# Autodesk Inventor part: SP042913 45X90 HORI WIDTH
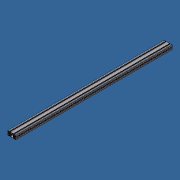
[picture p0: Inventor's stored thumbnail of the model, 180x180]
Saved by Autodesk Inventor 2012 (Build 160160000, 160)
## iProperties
Created: 2013-04
Part Number: SP042913 45X90 HORI WIDTH
Material: Aluminum-6061
Description: PROFILE 45X90 F
Document SubType Name: Modeling
Designer: Admin
Stock Number: 20.1032 PROFILE 45X90 F
Density: 2.71 g/cm^3
FINISH: CLEAR ANODIZED
Author: Admin
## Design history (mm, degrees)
sketch "Sketch1"
  geometry: L1 (43, -8.8)-(43, -15.5) reference; L2 (38, -20.5)-(31.3, -20.5) reference; L3 (31.3, -20.5)-(31.3, -13.8) reference; L4 (36.3, -8.8)-(43, -8.8) reference; L5 (-43, 8.8)-(-43, 15.5) reference; L6 (-38, 20.5)-(-31.3, 20.5) reference; L7 (-31.3, 20.5)-(-31.3, 13.8) reference; L8 (-36.3, 8.8)-(-43, 8.8) reference; L9 (43, 15.5)-(43, 8.8) reference; L10 (43, 8.8)-(36.3, 8.8) reference; L11 (31.3, 13.8)-(31.3, 20.5) reference; L12 (31.3, 20.5)-(38, 20.5) reference; L13 (-43, -15.5)-(-43, -8.8) reference; L14 (-43, -8.8)-(-36.3, -8.8) reference; L15 (-31.3, -13.8)-(-31.3, -20.5) reference; L16 (-31.3, -20.5)-(-38, -20.5) reference; L17 (-25.682, -4.596)-(-27.096, -3.182) reference; L18 (-27.096, -3.182)-(-25.763, -1.849) reference; L19 (-25.763, 1.849)-(-27.096, 3.182) reference; L20 (-27.096, 3.182)-(-25.682, 4.596) reference; L21 (-25.682, 4.596)-(-24.349, 3.263) reference; L22 (-20.651, 3.263)-(-19.318, 4.596) reference; L23 (-19.318, 4.596)-(-17.904, 3.182) reference; L24 (-17.904, 3.182)-(-19.237, 1.849) reference; L25 (-19.237, -1.849)-(-17.904, -3.182) reference; L26 (-17.904, -3.182)-(-19.318, -4.596) reference; L27 (-19.318, -4.596)-(-20.651, -3.263) reference; L28 (-24.349, -3.263)-(-25.682, -4.596) reference; L29 (19.318, -4.596)-(17.904, -3.182) reference; L30 (17.904, -3.182)-(19.237, -1.849) reference; L31 (19.237, 1.849)-(17.904, 3.182) reference; L32 (17.904, 3.182)-(19.318, 4.596) reference; L33 (19.318, 4.596)-(20.651, 3.263) reference; L34 (24.349, 3.263)-(25.682, 4.596) reference; L35 (25.682, 4.596)-(27.096, 3.182) reference; L36 (27.096, 3.182)-(25.763, 1.849) reference; L37 (25.763, -1.849)-(27.096, -3.182) reference; L38 (27.096, -3.182)-(25.682, -4.596) reference; L39 (25.682, -4.596)-(24.349, -3.263) reference; L40 (20.651, -3.263)-(19.318, -4.596) reference; L41 (-14.286, -7.786)-(-14.914, -7.157) reference; L42 (-15.5, -5.743)-(-15.5, 5.743) reference; L43 (-14.914, 7.157)-(-14.286, 7.786) reference; L44 (-13.7, 9.2)-(-13.7, 20.5) reference; L45 (-13.7, 20.5)-(13.7, 20.5) reference; L46 (13.7, 20.5)-(13.7, 9.2) reference; L47 (14.286, 7.786)-(14.914, 7.157) reference; L48 (15.5, 5.743)-(15.5, -5.743) reference; L49 (14.914, -7.157)-(14.286, -7.786) reference; L50 (13.7, -9.2)-(13.7, -20.5) reference; L51 (13.7, -20.5)-(-13.7, -20.5) reference; L52 (-13.7, -20.5)-(-13.7, -9.2) reference; L53 (26.6, 22.5)-(26.6, 18) reference; L54 (29.3, 18)-(29.3, 9.5) reference; L55 (29.3, 9.5)-(27, 7.2) reference; L56 (27, 7.2)-(18, 7.2) reference; L57 (18, 7.2)-(15.7, 9.5) reference; L58 (15.7, 9.5)-(15.7, 18) reference; L59 (15.7, 18)-(17.9, 18) reference; L60 (18.4, 18)-(18.4, 22.5) reference; L61 (-18.4, 22.5)-(-18.4, 18) reference; L62 (-15.7, 18)-(-15.7, 9.5) reference; L63 (-15.7, 9.5)-(-18, 7.2) reference; L64 (-18, 7.2)-(-27, 7.2) reference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; A1 r 5 centre (38, -15.5) between (38, -20.5) and (43, -15.5) reference; A2 r 5 centre (36.3, -13.8) between (36.3, -8.8) and (31.3, -13.8) reference; A3 r 5 centre (-38, 15.5) between (-38, 20.5) and (-43, 15.5) reference; A4 r 5 centre (-36.3, 13.8) between (-36.3, 8.8) and (-31.3, 13.8) reference; A5 r 5 centre (36.3, 13.8) between (31.3, 13.8) and (36.3, 8.8) reference; A6 r 5 centre (38, 15.5) between (43, 15.5) and (38, 20.5) reference; A7 r 5 centre (-36.3, -13.8) between (-31.3, -13.8) and (-36.3, -8.8) reference; A8 r 5 centre (-38, -15.5) between (-43, -15.5) and (-38, -20.5) reference; A9 r 3.75 centre (-22.5, 0) between (-24.16, -3.362) and (-20.84, -3.362) reference; A10 r 3.75 centre (22.5, 0) between (25.862, -1.66) and (25.862, 1.66) reference; A11 r 2 centre (-15.7, -9.2) between (-13.7, -9.2) and (-14.286, -7.786) reference; A12 r 2 centre (-13.5, -5.743) between (-15.5, -5.743) and (-14.914, -7.157) reference; A13 r 2 centre (-13.5, 5.743) between (-14.914, 7.157) and (-15.5, 5.743) reference; A14 r 2 centre (-15.7, 9.2) between (-14.286, 7.786) and (-13.7, 9.2) reference; A15 r 2 centre (15.7, 9.2) between (13.7, 9.2) and (14.286, 7.786) reference; A16 r 2 centre (13.5, 5.743) between (15.5, 5.743) and (14.914, 7.157) reference; A17 r 2 centre (13.5, -5.743) between (14.914, -7.157) and (15.5, -5.743) reference; A18 r 2 centre (15.7, -9.2) between (14.286, -7.786) and (13.7, -9.2) reference; A19 r 3.75 centre (-22.5, 0) between (-25.763, 1.849) and (-25.862, 1.66) reference; A20 r 3.75 centre (-22.5, 0) between (-25.862, 1.66) and (-25.763, -1.849) reference; A21 r 3.75 centre (-22.5, 0) between (-24.349, -3.263) and (-24.16, -3.362) reference; A22 r 3.75 centre (-22.5, 0) between (-19.138, 1.66) and (-19.237, 1.849) reference; A23 r 3.75 centre (-22.5, 0) between (-20.651, 3.263) and (-24.349, 3.263) reference; A24 r 3.75 centre (-22.5, 0) between (-20.84, -3.362) and (-20.651, -3.263) reference; A25 r 3.75 centre (-22.5, 0) between (-19.237, -1.849) and (-19.138, 1.66) reference; A26 r 3.75 centre (22.5, 0) between (20.84, 3.362) and (20.651, 3.263) reference; A27 r 3.75 centre (22.5, 0) between (19.237, 1.849) and (19.237, -1.849) reference; A28 r 3.75 centre (22.5, 0) between (20.651, -3.263) and (20.84, -3.362) reference; A29 r 3.75 centre (22.5, 0) between (20.84, -3.362) and (24.349, -3.263) reference; A30 r 3.75 centre (22.5, 0) between (25.763, -1.849) and (25.862, -1.66) reference; A31 r 3.75 centre (22.5, 0) between (25.862, 1.66) and (25.763, 1.849) reference; A32 r 3.75 centre (22.5, 0) between (24.349, 3.263) and (20.84, 3.362) reference
  constraints: 258 end point, 64 point on circle, 40 horizontal, 37 vertical, 32 centre point, 2 point on line, 269 other
extrude "Extrusion1" new body sketch "Sketch1" stored distance "d0" = 1688 (computed from Width, TOP_OVERHANG); taper "d1" = 0 deg
body "Solid1"
other parameters: "Height" = 1066.8 [user parameter], "Width" = 1828.8 [user parameter; used in 1 equation term], "DEPTH" = 914.4 [user parameter], "LOWER_INSET" = 203.2 [user parameter], "TABLE_TOP_THICKNESS" = 12.7 [user parameter], "LEVELER_HEIGHT" = 44.45 [user parameter], "TOP_OVERHANG" = 25.4 [user parameter; used in 1 equation term]
